// SIMATIC S7-200 SMART project (STEP 7-Micro/WIN SMART), CPU ST60

SYMBOL_TABLE MAIN
MBUS_ZPos        VD3008
MBUS_YPos        VD3004
MBSServerErr     VB1100
MBSServerDone    M6.0
MBUSTCP_Adress   VD3000
BreakOut         M0.3
AxisXJogCmd      M1.0
AxisXJogPCmd     M1.1
AxisXJogNCmd     M1.2
AxisXJogDirCmd   M1.3
AxisXJogDir      M1.4
AxisY_JogCmd     M2.0
AxisY_JogPCmd    M2.1
AxisY_JogNCmd    M2.2
AxisYJogDirCmd   M2.3
AxisY_JogDir     M2.4
AxisZ_JogCmd     M3.0
AxisZ_JogPCmd    M3.1
AxisZ_JogNCmd    M3.2
AxisZJogDirCmd   M3.3
AxisZ_JogDir     M3.4
GrpRst           M4.0
GrpRstBusy       M4.1
GrpRstDone       M4.2
StartCircle      M5.0     // 画圆启动按钮
CircleDone       M5.1
CircleBusy       M5.2
CircleActive     M5.3
AxisXJogErr      VB1030
AxisY_JogErr     VB1040
AxisZ_JogErr     VB1050
GrpRstErr        VB1060
CircleErr        VB1088
JogSpeedCmd      VD1024
AxisXJogPos      VD1032
AxisXJogSpeed    VD1036
AxisY_JogPos     VD1042
AxisY_JogSpeed   VD1046
AxisZ_JogPos     VD1052
AxisZ_JogSpeed   VD1056
CircleSpeedSet   VD1064   // HMI设定的画圆速度
X1Set            VD1068   // HMI设定的起点坐标X
εSet             VD1072   // HMI设定的ε
Y1Set            VD1076   // HMI设定的起点坐标Y
XoSet            VD1080   // HMI设定的圆心坐标X
YoSet            VD1084   // HMI设定的圆心坐标Y
END_SYMBOL_TABLE

SYMBOL_TABLE 系统符号
Always_On        SM0.0    // 始终接通
First_Scan_On    SM0.1    // 仅在第一个扫描周期时接通
END_SYMBOL_TABLE

SYMBOL_TABLE IminationCircle
CurrY            VD2116   // 当次插补Y轴理论值
Curr△Y           VD2112   // 当前Y轴增量
SINCurr_α        VD2108   // SIN当前角度
CurrX            VD2104   // 当次插补X轴理论值
Curr△X           VD2100   // 当前X轴增量
COSCurr_α        VD2096   // COS当前角度
Curr_α           VD2092   // 当前角度
Curr△α           VD2088   // 当前角度增量
CurrNum          VD2084   // 当前插补次数n
∠PoPa            VD2080   // PoPa和X轴正方向的夹角
Cos∠PoPa         VD2076   // （Xa-Xo）/R
Radius           VD2072   // 圆的半径R
Xao2addYao2      VD2068   // （Xa-Xo）*（Xa-Xo）+（Ya-Yo）*（Ya-Yo）
Yao2             VD2064   // （Ya-Yo）*（Ya-Yo）
Xao2             VD2060   // （Xa-Xo）*（Xa-Xo）
Yao              VD2056   // Ya-Yo
Xao              VD2052   // Xa-Xo
Yo               VD2048   // 圆心PoY轴坐标
Xo               VD2044   // 圆心PoX轴坐标
Ya               VD2040   // 起点PaY轴坐标
Xa               VD2036   // 起点PaX轴坐标
IntpNum_INT      VD2032   // 插补次数（整数形式）
IntpNum_R        VD2028   // i：插补次数(实数)
Pi2              VD2024   // 2Π
△α               VD2020   // 单次插补的角度增量
Half△α           VD2016
Sqrt_εMul2Subε   VD2012   // √[ε（2-ε）]
εMul2Subε        VD2008   // ε（2-ε）
Sub2ε            VD2004   // 2-ε
ε                VD2000   // 相对误差=弦高/半径
LastIntpError    VB2124
IntpError        VB2122   // 插补错误
LastIntpDone     V2121.2
LastIntpBusy     V2121.1
LastIntpActive   V2121.0
IntpActive       V2120.3
IntpBusy         V2120.2
IntpDone         V2120.1
IntpNumber       VD2126   // 插补次数（实数）
LastIntp         V2120.0  // 最后一次插补中
END_SYMBOL_TABLE

SYMBOL_TABLE HMI
EnableAxes       M0.0
HomeAxes         M0.1
PosAxisX         VD1000
PosAxisY         VD1004
PosAxisZ         VD1008
SpdAxisX         VD1012
SpdAxisY         VD1016
SpdAxisZ         VD1020
END_SYMBOL_TABLE

ORGANIZATION_BLOCK MAIN:OB1
TITLE=header and description
// =============================================================================
// LIABILITY
// Siemens AG does not accept liability of any kind for damages arising from the use of this application, except where it is obliged to by law, in cases such as damage to items used for personal purposes, personal injury, willful damage or gross negligence.
// =============================================================================
// WARRANTY
// The program examples given are specific solutions to complex tasks which were worked on by Customer Support. We must also point out that it is not possible in the current state of the technology to exclude all errors in software programs under all conditions of use. The program examples were prepared according to the best of our knowledge. However, we cannot accept any liability beyond the standard guarantee for Class C software in accordance with our General Terms of Sale for Software Products for Automation and Drive Technology". The program examples can be purchased on the Internet as single licenses. They may not be transferred to a third party.
// 
BEGIN
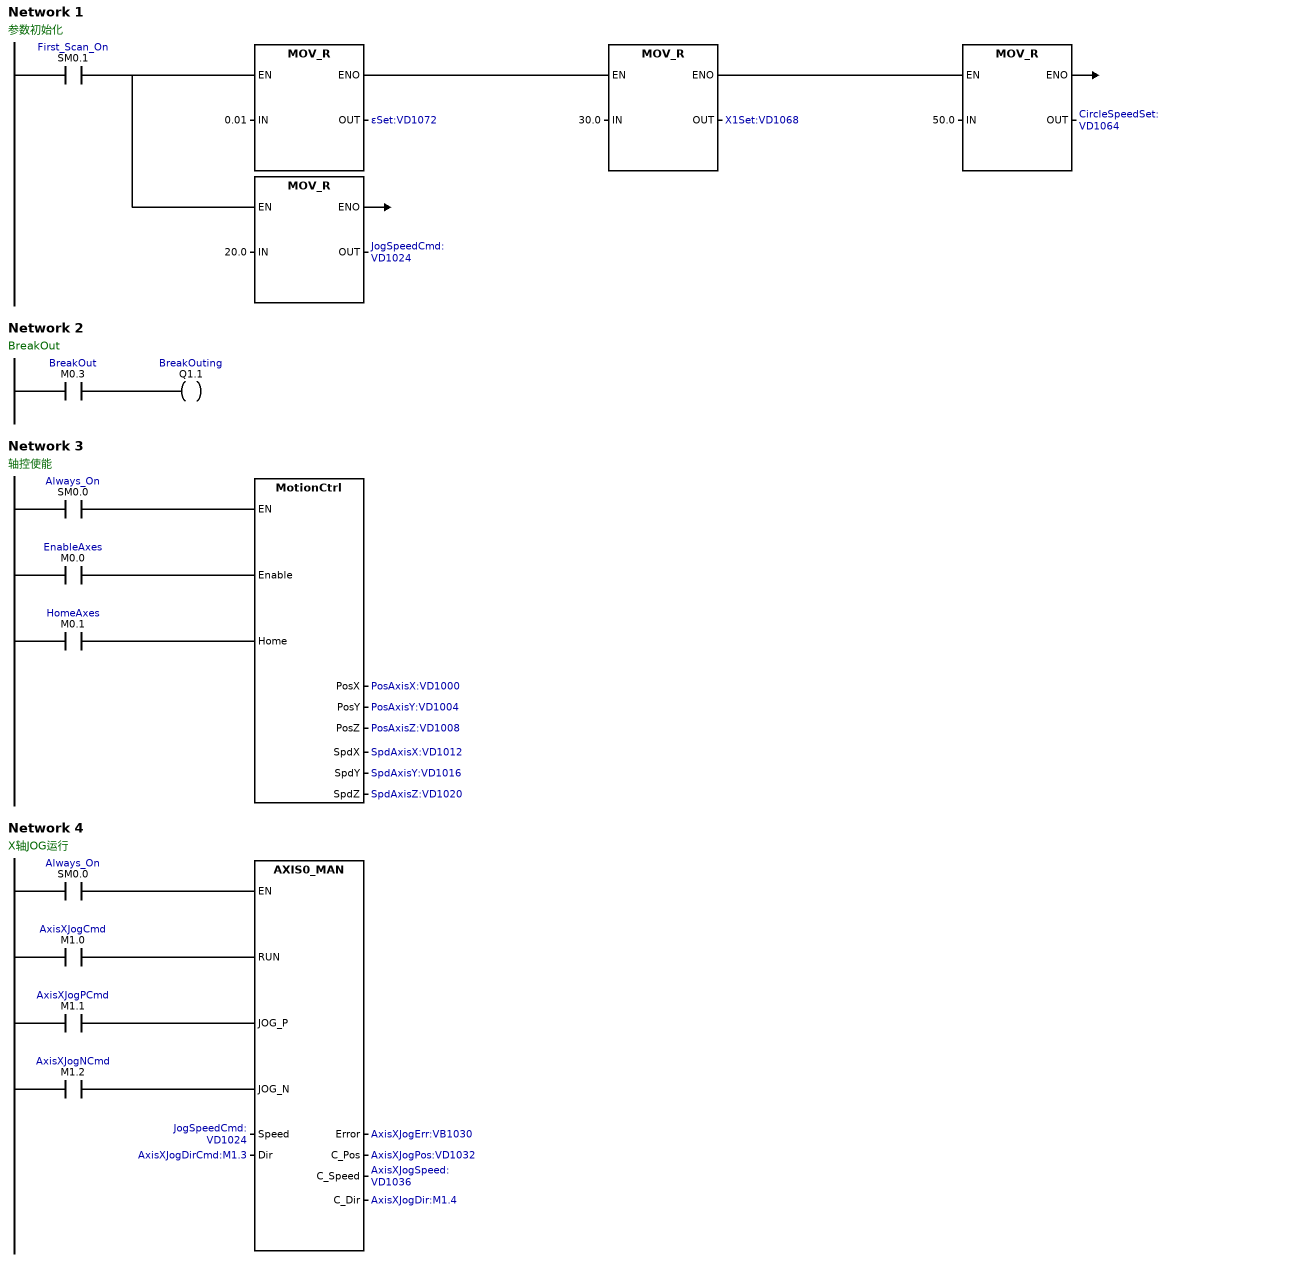
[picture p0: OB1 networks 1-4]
Network 1
// 参数初始化
LD     First_Scan_On:SM0.1
LPS
MOVR   0.01, εSet:VD1072
AENO
MOVR   30.0, X1Set:VD1068
AENO
MOVR   50.0, CircleSpeedSet:VD1064
LPP
MOVR   20.0, JogSpeedCmd:VD1024
Network 2
// BreakOut
LD     BreakOut:M0.3
=      BreakOuting:Q1.1
Network 3
// 轴控使能
LD     Always_On:SM0.0
=      L60.0
LD     EnableAxes:M0.0
=      L63.7
LD     HomeAxes:M0.1
=      L63.6
LD     L60.0
CALL   MotionCtrl:SBR35, L63.7, L63.6, PosAxisX:VD1000, PosAxisY:VD1004, PosAxisZ:VD1008, SpdAxisX:VD1012, SpdAxisY:VD1016, SpdAxisZ:VD1020
Network 4
// X轴JOG运行
LD     Always_On:SM0.0
=      L60.0
LD     AxisXJogCmd:M1.0
=      L63.7
LD     AxisXJogPCmd:M1.1
=      L63.6
LD     AxisXJogNCmd:M1.2
=      L63.5
LD     L60.0
CALL   AXIS0_MAN:SBR1, L63.7, L63.6, L63.5, JogSpeedCmd:VD1024, AxisXJogDirCmd:M1.3, AxisXJogErr:VB1030, AxisXJogPos:VD1032, AxisXJogSpeed:VD1036, AxisXJogDir:M1.4
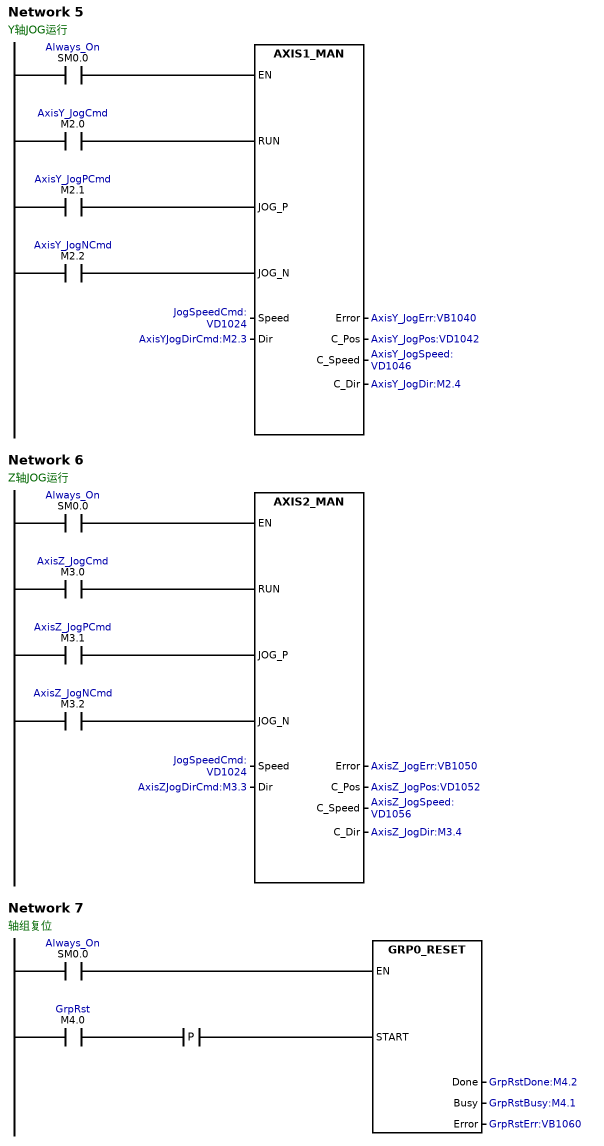
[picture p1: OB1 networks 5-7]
Network 5
// Y轴JOG运行
LD     Always_On:SM0.0
=      L60.0
LD     AxisY_JogCmd:M2.0
=      L63.7
LD     AxisY_JogPCmd:M2.1
=      L63.6
LD     AxisY_JogNCmd:M2.2
=      L63.5
LD     L60.0
CALL   AXIS1_MAN:SBR12, L63.7, L63.6, L63.5, JogSpeedCmd:VD1024, AxisYJogDirCmd:M2.3, AxisY_JogErr:VB1040, AxisY_JogPos:VD1042, AxisY_JogSpeed:VD1046, AxisY_JogDir:M2.4
Network 6
// Z轴JOG运行
LD     Always_On:SM0.0
=      L60.0
LD     AxisZ_JogCmd:M3.0
=      L63.7
LD     AxisZ_JogPCmd:M3.1
=      L63.6
LD     AxisZ_JogNCmd:M3.2
=      L63.5
LD     L60.0
CALL   AXIS2_MAN:SBR23, L63.7, L63.6, L63.5, JogSpeedCmd:VD1024, AxisZJogDirCmd:M3.3, AxisZ_JogErr:VB1050, AxisZ_JogPos:VD1052, AxisZ_JogSpeed:VD1056, AxisZ_JogDir:M3.4
Network 7
// 轴组复位
LD     Always_On:SM0.0
=      L60.0
LD     GrpRst:M4.0
EU
=      L63.7
LD     L60.0
CALL   GRP0_RESET:SBR34, L63.7, GrpRstDone:M4.2, GrpRstBusy:M4.1, GrpRstErr:VB1060
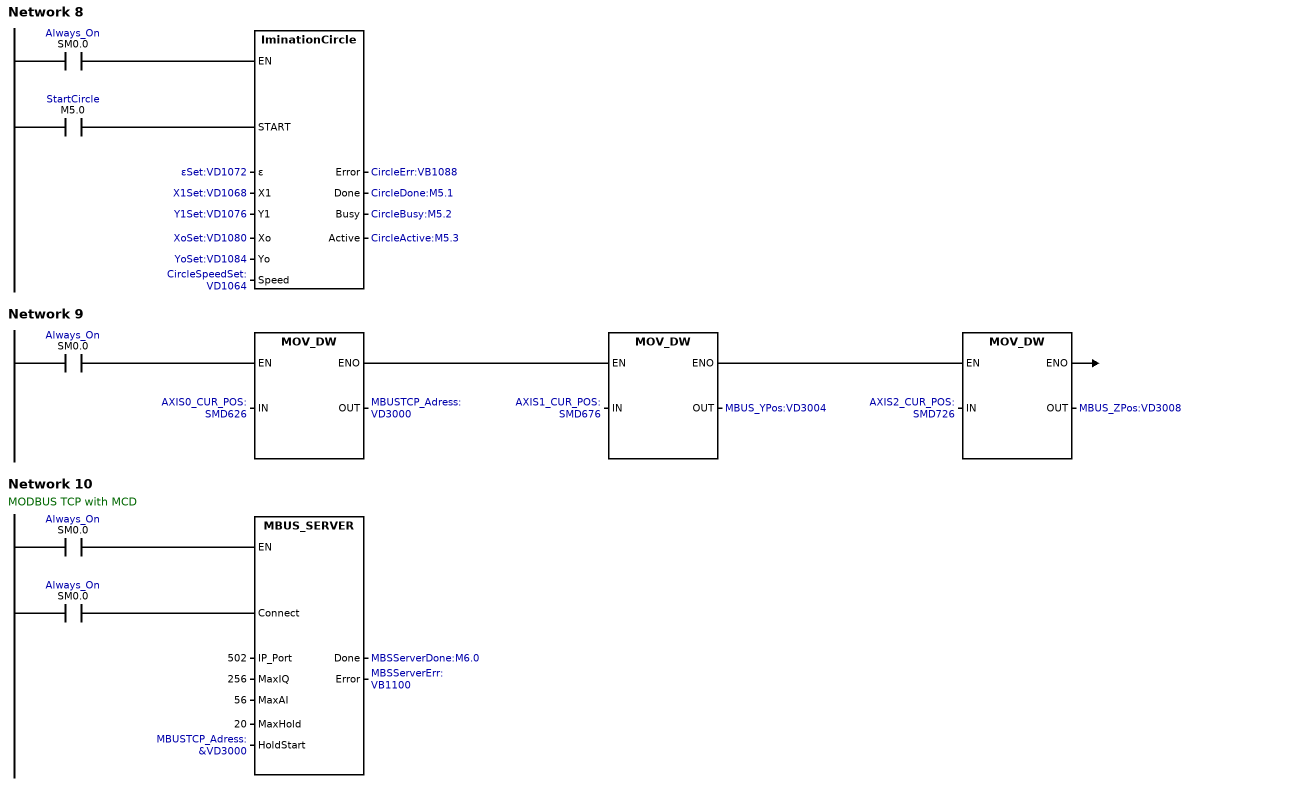
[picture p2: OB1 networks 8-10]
Network 8
LD     Always_On:SM0.0
=      L60.0
LD     StartCircle:M5.0
=      L63.7
LD     L60.0
CALL   IminationCircle:SBR126, L63.7, εSet:VD1072, X1Set:VD1068, Y1Set:VD1076, XoSet:VD1080, YoSet:VD1084, CircleSpeedSet:VD1064, CircleErr:VB1088, CircleDone:M5.1, CircleBusy:M5.2, CircleActive:M5.3
Network 9
LD     Always_On:SM0.0
MOVD   AXIS0_CUR_POS:SMD626, MBUSTCP_Adress:VD3000
AENO
MOVD   AXIS1_CUR_POS:SMD676, MBUS_YPos:VD3004
AENO
MOVD   AXIS2_CUR_POS:SMD726, MBUS_ZPos:VD3008
Network 10
// MODBUS TCP with MCD
LD     Always_On:SM0.0
=      L60.0
LD     Always_On:SM0.0
=      L63.7
LD     L60.0
CALL   MBUS_SERVER:SBR42, L63.7, 502, 256, 56, 20, &MBUSTCP_Adress:VD3000, MBSServerDone:M6.0, MBSServerErr:VB1100
END_ORGANIZATION_BLOCK

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
SUBROUTINE_BLOCK MotionCtrl:SBR35
TITLE=子程序注释
VAR_INPUT
Enable:BOOL;	// L0.0 
Home:BOOL;	// L0.1 
END_VAR
VAR_OUTPUT
PosX:REAL;	// LD1 
PosY:REAL;	// LD5 
PosZ:REAL;	// LD9 
SpdX:REAL;	// LD13 
SpdY:REAL;	// LD17 
SpdZ:REAL;	// LD21 
END_VAR
VAR
tempDone0:BOOL;	// L25.0 
tempDone1:BOOL;	// L25.1 
tempDone2:BOOL;	// L25.2 
tempErr0:BYTE;	// LB26 
tempErr1:BYTE;	// LB27 
tempErr2:BYTE;	// LB28 
tempPos:REAL;	// LD29 
tempSpd:REAL;	// LD33 
tempDir:BOOL;	// L37.0 
tempHome0:BOOL;	// L37.1 
tempHome1:BOOL;	// L37.2 
tempHome2:BOOL;	// L37.3 
END_VAR
BEGIN
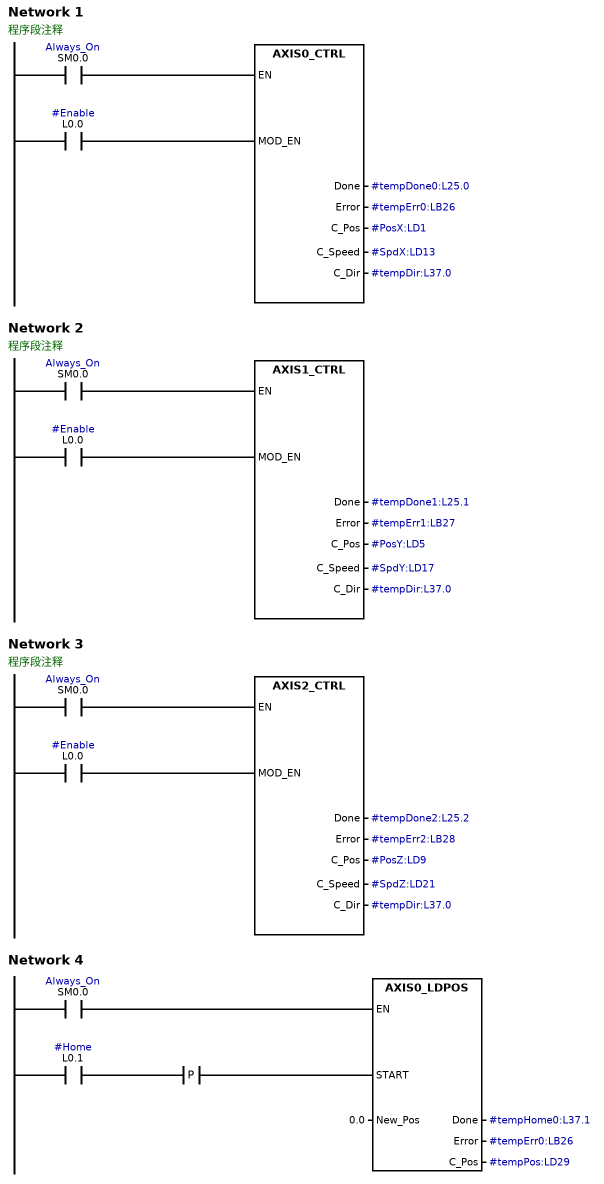
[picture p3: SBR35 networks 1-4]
Network 1
// 程序段注释
LD     Always_On:SM0.0
=      L60.0
LD     #Enable:L0.0
=      L63.7
LD     L60.0
CALL   AXIS0_CTRL:SBR0, L63.7, #tempDone0:L25.0, #tempErr0:LB26, #PosX:LD1, #SpdX:LD13, #tempDir:L37.0
Network 2
// 程序段注释
LD     Always_On:SM0.0
=      L60.0
LD     #Enable:L0.0
=      L63.7
LD     L60.0
CALL   AXIS1_CTRL:SBR11, L63.7, #tempDone1:L25.1, #tempErr1:LB27, #PosY:LD5, #SpdY:LD17, #tempDir:L37.0
Network 3
// 程序段注释
LD     Always_On:SM0.0
=      L60.0
LD     #Enable:L0.0
=      L63.7
LD     L60.0
CALL   AXIS2_CTRL:SBR22, L63.7, #tempDone2:L25.2, #tempErr2:LB28, #PosZ:LD9, #SpdZ:LD21, #tempDir:L37.0
Network 4
LD     Always_On:SM0.0
=      L60.0
LD     #Home:L0.1
EU
=      L63.7
LD     L60.0
CALL   AXIS0_LDPOS:SBR6, L63.7, 0.0, #tempHome0:L37.1, #tempErr0:LB26, #tempPos:LD29
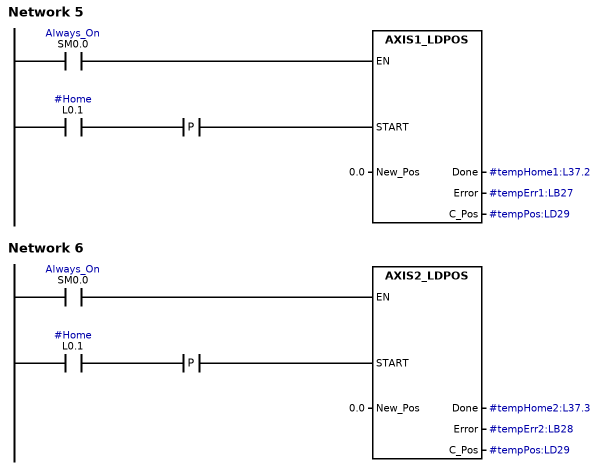
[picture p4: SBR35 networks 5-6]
Network 5
LD     Always_On:SM0.0
=      L60.0
LD     #Home:L0.1
EU
=      L63.7
LD     L60.0
CALL   AXIS1_LDPOS:SBR17, L63.7, 0.0, #tempHome1:L37.2, #tempErr1:LB27, #tempPos:LD29
Network 6
LD     Always_On:SM0.0
=      L60.0
LD     #Home:L0.1
EU
=      L63.7
LD     L60.0
CALL   AXIS2_LDPOS:SBR28, L63.7, 0.0, #tempHome2:L37.3, #tempErr2:LB28, #tempPos:LD29
END_SUBROUTINE_BLOCK

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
